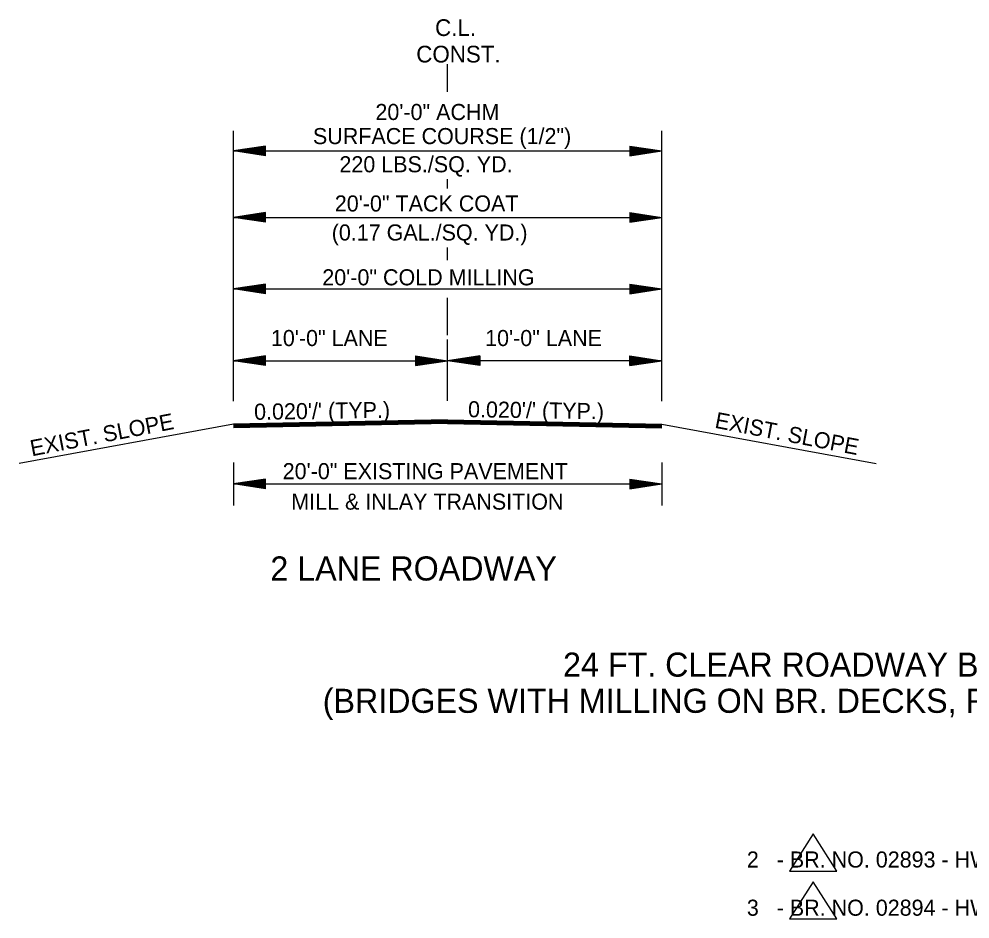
# Model space of a CAD drawing. Extents: x 544259 to 1930787, y -1961343 to 596640.
# Drawn here: x 544345.5 to 544789.4, y -1949576.9 to -1949157 of the extents above; entities that cross this region are included whole.
import ezdxf

# ---------------------------------------------------------------- set-up
doc = ezdxf.new("R2010")
doc.units = 0
doc.layers.add('R_Border', color=7, linetype='Continuous')
doc.layers.add('R_Draft', color=7, linetype='Continuous')

msp = doc.modelspace()

# ---------------------------------------------------------------- linework, layer by layer
at = {"layer": 'R_Border'}
for p, q in [((544716.22, -1949537.24), (544705.18, -1949554.55)), ((544727.26, -1949554.55), (544716.22, -1949537.24)), ((544705.18, -1949554.55), (544727.26, -1949554.55)), ((544716.22, -1949559.62), (544705.18, -1949576.93)), ((544727.26, -1949576.93), (544716.22, -1949559.62)), ((544705.18, -1949576.93), (544727.26, -1949576.93))]:
    msp.add_line(p, q, dxfattribs=at)
at = {"layer": 'R_Draft'}
for p, q in [((544545.54, -1949190.91), (544545.54, -1949177.96)), ((544445.54, -1949335.26), (544445.54, -1949209.19)), ((544645.54, -1949335.26), (544645.54, -1949209.19)), ((544460.54, -1949216.24), (544445.54, -1949218.49)), ((544460.54, -1949220.74), (544445.54, -1949218.49)), ((544445.54, -1949218.49), (544645.54, -1949218.49)), ((544460.54, -1949216.61), (544448.05, -1949218.49)), ((544460.54, -1949220.36), (544448.05, -1949218.49)), ((544460.54, -1949216.99), (544450.63, -1949218.49)), ((544460.54, -1949219.98), (544450.63, -1949218.49)), ((544460.54, -1949217.37), (544453.12, -1949218.49)), ((544460.54, -1949219.6), (544453.12, -1949218.49)), ((544460.54, -1949217.75), (544455.67, -1949218.49)), ((544460.54, -1949219.21), (544455.67, -1949218.49)), ((544460.54, -1949218.13), (544458.17, -1949218.49)), ((544460.54, -1949218.84), (544458.17, -1949218.49)), ((544460.54, -1949220.74), (544460.54, -1949216.24)), ((544630.54, -1949216.24), (544645.54, -1949218.49)), ((544630.54, -1949216.24), (544630.54, -1949220.74)), ((544630.54, -1949216.61), (544643.04, -1949218.49)), ((544630.54, -1949216.99), (544640.46, -1949218.49)), ((544630.54, -1949217.37), (544637.96, -1949218.49)), ((544630.54, -1949217.76), (544635.42, -1949218.49)), ((544630.54, -1949218.13), (544632.91, -1949218.49)), ((544630.54, -1949220.74), (544645.54, -1949218.49)), ((544630.54, -1949219.22), (544635.42, -1949218.49)), ((544630.54, -1949219.98), (544640.46, -1949218.49)), ((544630.54, -1949220.36), (544643.04, -1949218.49)), ((544630.54, -1949219.6), (544637.96, -1949218.49)), ((544630.54, -1949218.84), (544632.91, -1949218.49)), ((544545.54, -1949236.05), (544545.54, -1949231.65)), ((544460.54, -1949247.28), (544445.54, -1949249.53)), ((544460.54, -1949251.78), (544445.54, -1949249.53)), ((544445.54, -1949249.53), (544645.54, -1949249.53)), ((544460.54, -1949247.66), (544448.05, -1949249.53)), ((544460.54, -1949251.41), (544448.05, -1949249.53)), ((544460.54, -1949248.04), (544450.63, -1949249.53)), ((544460.54, -1949251.02), (544450.63, -1949249.53)), ((544460.54, -1949248.41), (544453.12, -1949249.53)), ((544460.54, -1949250.65), (544453.12, -1949249.53)), ((544460.54, -1949248.8), (544455.67, -1949249.53)), ((544460.54, -1949250.26), (544455.67, -1949249.53)), ((544460.54, -1949249.18), (544458.17, -1949249.53)), ((544460.54, -1949249.88), (544458.17, -1949249.53)), ((544460.54, -1949251.78), (544460.54, -1949247.28)), ((544630.54, -1949247.28), (544645.54, -1949249.53)), ((544630.54, -1949247.28), (544630.54, -1949251.78)), ((544630.54, -1949247.66), (544643.04, -1949249.53)), ((544630.54, -1949248.04), (544640.46, -1949249.53)), ((544630.54, -1949248.41), (544637.96, -1949249.53)), ((544630.54, -1949248.8), (544635.42, -1949249.53)), ((544630.54, -1949249.18), (544632.91, -1949249.53)), ((544630.54, -1949251.78), (544645.54, -1949249.53)), ((544630.54, -1949250.27), (544635.42, -1949249.53)), ((544630.54, -1949251.02), (544640.46, -1949249.53)), ((544630.54, -1949251.41), (544643.04, -1949249.53)), ((544630.54, -1949250.65), (544637.96, -1949249.53)), ((544630.54, -1949249.88), (544632.91, -1949249.53)), ((544545.54, -1949269.52), (544545.54, -1949263.58)), ((544460.54, -1949280.65), (544445.54, -1949282.9)), ((544460.54, -1949285.15), (544460.54, -1949280.65)), ((544630.54, -1949280.65), (544645.54, -1949282.9)), ((544630.54, -1949280.65), (544630.54, -1949285.15)), ((544445.54, -1949282.9), (544645.54, -1949282.9)), ((544460.54, -1949285.15), (544445.54, -1949282.9)), ((544460.54, -1949281.02), (544448.05, -1949282.9)), ((544460.54, -1949284.77), (544448.05, -1949282.9)), ((544460.54, -1949281.41), (544450.63, -1949282.9)), ((544460.54, -1949284.39), (544450.63, -1949282.9)), ((544460.54, -1949281.78), (544453.12, -1949282.9)), ((544460.54, -1949284.02), (544453.12, -1949282.9)), ((544460.54, -1949282.16), (544455.67, -1949282.9)), ((544460.54, -1949283.63), (544455.67, -1949282.9)), ((544460.54, -1949282.55), (544458.17, -1949282.9)), ((544460.54, -1949283.25), (544458.17, -1949282.9)), ((544630.54, -1949281.02), (544643.04, -1949282.9)), ((544630.54, -1949281.41), (544640.46, -1949282.9)), ((544630.54, -1949281.78), (544637.96, -1949282.9)), ((544630.54, -1949282.17), (544635.42, -1949282.9)), ((544630.54, -1949282.55), (544632.91, -1949282.9)), ((544630.54, -1949285.15), (544645.54, -1949282.9)), ((544630.54, -1949283.63), (544635.42, -1949282.9)), ((544630.54, -1949284.39), (544640.46, -1949282.9)), ((544630.54, -1949284.77), (544643.04, -1949282.9)), ((544630.54, -1949284.02), (544637.96, -1949282.9)), ((544630.54, -1949283.25), (544632.91, -1949282.9)), ((544545.54, -1949294.55), (544545.54, -1949287.14)), ((544545.54, -1949304.42), (544545.54, -1949294.55)), ((544545.54, -1949335.09), (544545.54, -1949306.54)), ((544460.54, -1949314.19), (544445.54, -1949316.44)), ((544460.54, -1949314.56), (544448.05, -1949316.44)), ((544460.54, -1949314.94), (544450.63, -1949316.44)), ((544460.54, -1949315.32), (544453.12, -1949316.44)), ((544460.54, -1949315.7), (544455.67, -1949316.44)), ((544460.54, -1949316.08), (544458.17, -1949316.44)), ((544460.54, -1949318.69), (544460.54, -1949314.19)), ((544530.54, -1949314.19), (544545.54, -1949316.44)), ((544530.54, -1949314.19), (544530.54, -1949318.69)), ((544530.54, -1949314.56), (544543.04, -1949316.44)), ((544530.54, -1949314.94), (544540.46, -1949316.44)), ((544530.54, -1949315.32), (544537.96, -1949316.44)), ((544530.54, -1949315.71), (544535.42, -1949316.44)), ((544530.54, -1949316.08), (544532.91, -1949316.44)), ((544560.54, -1949314.19), (544545.54, -1949316.44)), ((544560.54, -1949314.56), (544548.05, -1949316.44)), ((544560.54, -1949314.94), (544550.63, -1949316.44)), ((544560.54, -1949315.32), (544553.12, -1949316.44)), ((544560.54, -1949315.71), (544555.67, -1949316.44)), ((544560.54, -1949316.08), (544558.17, -1949316.44)), ((544560.54, -1949314.19), (544560.54, -1949318.69)), ((544630.54, -1949314.19), (544645.54, -1949316.44)), ((544630.54, -1949318.69), (544630.54, -1949314.19)), ((544630.54, -1949314.56), (544643.04, -1949316.44)), ((544630.54, -1949314.94), (544640.46, -1949316.44)), ((544630.54, -1949315.32), (544637.96, -1949316.44)), ((544630.54, -1949315.7), (544635.42, -1949316.44)), ((544630.54, -1949316.08), (544632.91, -1949316.44)), ((544460.54, -1949318.69), (544445.54, -1949316.44)), ((544445.54, -1949316.44), (544545.54, -1949316.44)), ((544460.54, -1949318.31), (544448.05, -1949316.44)), ((544460.54, -1949317.93), (544450.63, -1949316.44)), ((544460.54, -1949317.55), (544453.12, -1949316.44)), ((544460.54, -1949317.16), (544455.67, -1949316.44)), ((544460.54, -1949316.79), (544458.17, -1949316.44)), ((544530.54, -1949318.69), (544545.54, -1949316.44)), ((544530.54, -1949317.17), (544535.42, -1949316.44)), ((544530.54, -1949317.93), (544540.46, -1949316.44)), ((544530.54, -1949318.31), (544543.04, -1949316.44)), ((544530.54, -1949317.55), (544537.96, -1949316.44)), ((544530.54, -1949316.79), (544532.91, -1949316.44)), ((544645.54, -1949316.44), (544545.54, -1949316.44)), ((544560.54, -1949318.69), (544545.54, -1949316.44)), ((544560.54, -1949318.31), (544548.05, -1949316.44)), ((544560.54, -1949317.93), (544550.63, -1949316.44)), ((544560.54, -1949317.55), (544553.12, -1949316.44)), ((544560.54, -1949317.17), (544555.67, -1949316.44)), ((544560.54, -1949316.79), (544558.17, -1949316.44)), ((544630.54, -1949318.69), (544645.54, -1949316.44)), ((544630.54, -1949317.16), (544635.42, -1949316.44)), ((544630.54, -1949317.93), (544640.46, -1949316.44)), ((544630.54, -1949318.31), (544643.04, -1949316.44)), ((544630.54, -1949317.55), (544637.96, -1949316.44)), ((544630.54, -1949316.79), (544632.91, -1949316.44)), ((544445.54, -1949346.04), (544345.47, -1949364.42)), ((544545.54, -1949344.04), (544445.54, -1949346.04)), ((544545.55, -1949344.34), (544445.54, -1949346.34)), ((544545.55, -1949344.64), (544445.54, -1949346.64)), ((544545.56, -1949344.94), (544445.54, -1949346.94)), ((544545.56, -1949345.24), (544445.54, -1949347.24)), ((544545.57, -1949345.54), (544445.54, -1949347.54)), ((544545.57, -1949345.71), (544445.54, -1949347.74)), ((544545.51, -1949345.54), (544645.54, -1949347.54)), ((544545.51, -1949345.71), (544645.54, -1949347.71)), ((544545.52, -1949344.94), (544645.54, -1949346.94)), ((544545.52, -1949345.24), (544645.54, -1949347.24)), ((544545.53, -1949344.34), (544645.54, -1949346.34)), ((544545.53, -1949344.64), (544645.54, -1949346.64)), ((544545.54, -1949344.04), (544645.54, -1949346.04)), ((544645.54, -1949346.04), (544745.61, -1949364.42)), ((544445.54, -1949363.9), (544445.54, -1949383.9)), ((544645.54, -1949363.9), (544645.54, -1949383.9)), ((544460.54, -1949371.65), (544445.54, -1949373.9)), ((544445.54, -1949373.9), (544645.54, -1949373.9)), ((544460.54, -1949376.15), (544445.54, -1949373.9)), ((544460.54, -1949372.03), (544448.05, -1949373.9)), ((544460.54, -1949375.78), (544448.05, -1949373.9)), ((544460.54, -1949372.41), (544450.63, -1949373.9)), ((544460.54, -1949375.39), (544450.63, -1949373.9)), ((544460.54, -1949372.78), (544453.12, -1949373.9)), ((544460.54, -1949375.02), (544453.12, -1949373.9)), ((544460.54, -1949373.17), (544455.67, -1949373.9)), ((544460.54, -1949374.63), (544455.67, -1949373.9)), ((544460.54, -1949373.55), (544458.17, -1949373.9)), ((544460.54, -1949374.25), (544458.17, -1949373.9)), ((544460.54, -1949376.15), (544460.54, -1949371.65)), ((544630.54, -1949371.65), (544645.54, -1949373.9)), ((544630.54, -1949371.65), (544630.54, -1949376.15)), ((544630.54, -1949372.03), (544643.04, -1949373.9)), ((544630.54, -1949372.41), (544640.46, -1949373.9)), ((544630.54, -1949372.78), (544637.96, -1949373.9)), ((544630.54, -1949373.17), (544635.42, -1949373.9)), ((544630.54, -1949373.55), (544632.91, -1949373.9)), ((544630.54, -1949376.15), (544645.54, -1949373.9)), ((544630.54, -1949374.64), (544635.42, -1949373.9)), ((544630.54, -1949375.39), (544640.46, -1949373.9)), ((544630.54, -1949375.78), (544643.04, -1949373.9)), ((544630.54, -1949375.02), (544637.96, -1949373.9)), ((544630.54, -1949374.25), (544632.91, -1949373.9))]:
    msp.add_line(p, q, dxfattribs=at)

# ---------------------------------------------------------------- texts
for s, height, p in [('C.L.', 7.8, (544539.69, -1949164.87)), ('CONST.', 7.8, (544530.91, -1949177.24)), ('20\'-0" ACHM ', 7.5, (544511.85, -1949204.08)), ('SURFACE COURSE (1/2")', 7.5, (544482.68, -1949215.33)), ('220 LBS./SQ. YD. ', 7.5, (544495.05, -1949228.48)), ('20\'-0" TACK COAT', 7.5, (544492.89, -1949246.77)), ('(0.17 GAL./SQ. YD.)', 7.5, (544491.45, -1949260.31)), ('20\'-0" COLD MILLING', 7.5, (544487.05, -1949281.23)), ('10\'-0" LANE', 7.5, (544463.06, -1949309.57)), ('10\'-0" LANE', 7.5, (544563.06, -1949309.57)), ('20\'-0" EXISTING PAVEMENT', 7.5, (544468.56, -1949371.69)), ('MILL & INLAY TRANSITION', 7.5, (544472.57, -1949385.91)), ('2 LANE ROADWAY', 11.25, (544462.81, -1949418.98)), ('24 FT. CLEAR ROADWAY BRIDGES - HYDRODEMOLITION', 11.25, (544599.45, -1949463.85)), ('(BRIDGES WITH MILLING ON BR. DECKS, ROAD TRANSITIONS, AND NEW GUARDRAIL)', 11.25, (544487.26, -1949480.73)), ('      2   - BR. NO. 02893 - HWY. 114       2"', 7.5, (544668.53, -1949552.92)), ('      3   - BR. NO. 02894 - HWY. 114       2"', 7.5, (544668.53, -1949575.42))]:
    msp.add_text(s, height=height, dxfattribs=at).set_placement(p)
for s, rotation, p in [("0.020'/' (TYP.)", 0.8719, (544455.27, -1949344)), ("0.020'/' (TYP.)", 359.1281, (544555.04, -1949342.77)), ('EXIST. SLOPE', 10.8829, (544351.45, -1949361.04)), ('EXIST. SLOPE', 349.1171, (544669.92, -1949347.64))]:
    msp.add_text(s, height=7.5, rotation=rotation, dxfattribs=at).set_placement(p)

doc.saveas('drawing.dxf')
